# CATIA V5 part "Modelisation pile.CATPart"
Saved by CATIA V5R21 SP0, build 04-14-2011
Part number: Modelisation pile
Bounding box of the stored display mesh (mm): x 0 to 78.3, y 0 to 62, z 0 to 30
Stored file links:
  C:\Users\2027.DESARCY-LEMIE30\Desktop\V15(20.03.2023)\Modelisation pile.CATPart
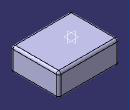
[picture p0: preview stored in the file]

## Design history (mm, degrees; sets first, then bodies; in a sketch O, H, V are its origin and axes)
Body1 (main body)
  Sketch1 on xy-plane, origin (0, 0, 0), H (1, 0, 0), V (0, 1, 0)
    line L1 (0, 62) -> (78.3, 62)
    line L2 (78.3, 62) -> (78.3, 0)
    line L3 (78.3, 0) -> (0, 0)
    line L4 (0, 0) -> (0, 62)
    point P3 (78.3, 0)
    point P4 (0, 0)
    length L2 = 62
    length L3 = 78.3
    horizontal: L1 H, L3 H
    vertical: L2 V, L4 V
    coincidence: P3 H, P4 O
  Pad1: profile Sketch1, direction (0, 0, 1), length 30
  Fillet1: radius 3, on edge [face of Pad1 from Sketch1.L4 | end face of Pad1]; edge [face of Pad1 from Sketch1.L1 | end face of Pad1]; edge [face of Pad1 from Sketch1.L3 | end face of Pad1]; edge [face of Pad1 from Sketch1.L2 | end face of Pad1]
  Fillet2: radius 3, on edge [start face of Pad1 | face of Pad1 from Sketch1.L1]; edge [start face of Pad1 | face of Pad1 from Sketch1.L4]; edge [start face of Pad1 | face of Pad1 from Sketch1.L3]; edge [start face of Pad1 | face of Pad1 from Sketch1.L2]
  Fillet3: radius 3, on edge [face of Pad1 from Sketch1.L3 | face of Pad1 from Sketch1.L4]; edge [face of Pad1 from Sketch1.L1 | face of Pad1 from Sketch1.L2]; edge [face of Pad1 from Sketch1.L2 | face of Pad1 from Sketch1.L3]; edge [face of Pad1 from Sketch1.L4 | face of Pad1 from Sketch1.L1]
